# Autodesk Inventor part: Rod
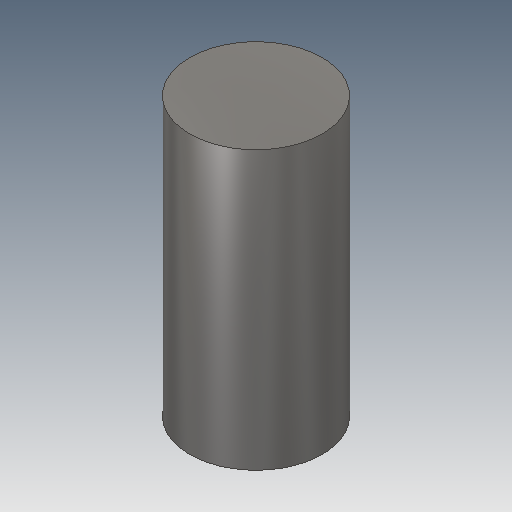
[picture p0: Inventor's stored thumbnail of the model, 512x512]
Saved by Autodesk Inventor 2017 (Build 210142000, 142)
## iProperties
Created: 2016-08
Part Number: Rod
Material: Steel, Mild
Document SubType Name: Modeling
Designer: Gaurav
Density: 7.85 g/cm^3
Appearance: Semi-Polished
Author: Gaurav
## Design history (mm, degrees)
sketch "Sketch1"
  geometry: C1 r 9 at (0, 0); 1 further point
  constraints: 1 centre point, 1 coincident
  dimensions: "d0" = 18 diameter of C1
extrude "Extrusion1" new body sketch "Sketch1" distance "d1" = 37.75; taper "d2" = 0 deg
body "Solid1"
